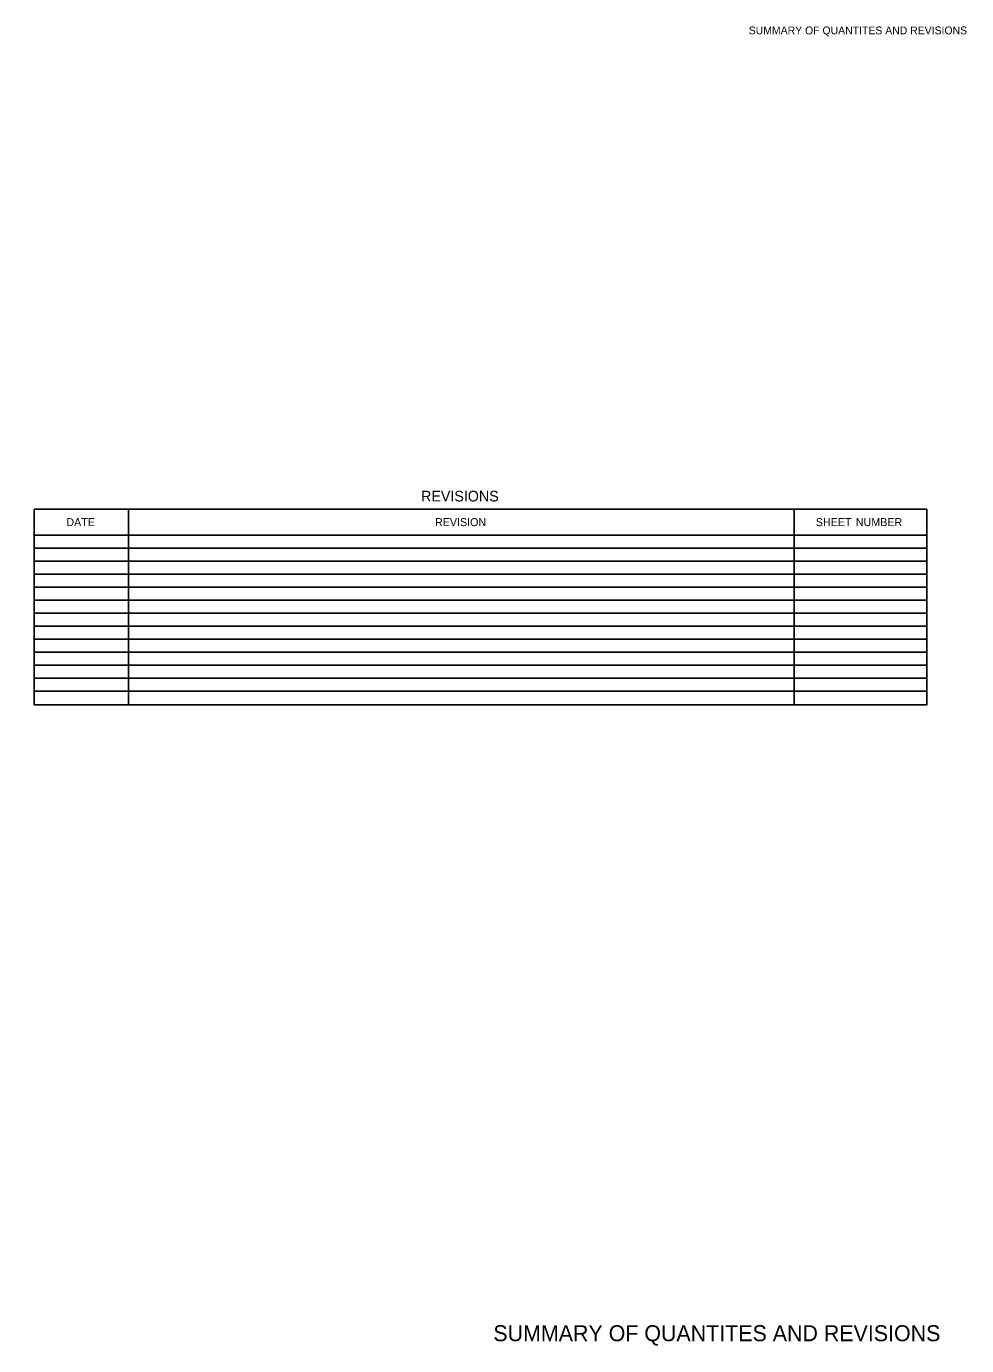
# Model space of a CAD drawing. Extents: x 977434 to 989596, y 1525697 to 1528336.
# Drawn here: x 988891 to 989596, y 1527332 to 1528321 of the extents above; entities that cross this region are included whole.
import ezdxf

# ---------------------------------------------------------------- set-up
doc = ezdxf.new("R2010")
doc.units = 0
for name, color, linetype in [('Default', 7, 'Continuous'), ('R_Border', 7, 'Continuous'), ('R_Border Prem', 7, 'Continuous')]:
    doc.layers.add(name, color=color, linetype=linetype)

msp = doc.modelspace()

# ---------------------------------------------------------------- linework, layer by layer
at = {"layer": 'Default'}
for p, q in [((988896.68, 1527958.98), (989566.02, 1527958.98)), ((988896.68, 1527958.98), (988967.37, 1527958.98)), ((988896.68, 1527812.24), (988896.68, 1527958.98)), ((988896.68, 1527812.24), (988896.68, 1527958.98)), ((988967.37, 1527812.24), (988967.37, 1527958.98)), ((989466.57, 1527958.98), (989566.02, 1527958.98)), ((989466.57, 1527939.48), (989466.57, 1527958.98)), ((989466.57, 1527812.24), (989466.57, 1527958.98)), ((989566.02, 1527812.24), (989566.02, 1527958.98)), ((989566.02, 1527812.24), (989566.02, 1527958.98)), ((988896.68, 1527939.48), (989566.02, 1527939.48)), ((988896.68, 1527929.73), (989566.02, 1527929.73)), ((988896.68, 1527919.98), (989566.02, 1527919.98)), ((988896.68, 1527910.23), (989566.02, 1527910.23)), ((988896.68, 1527900.48), (989566.02, 1527900.48)), ((988896.68, 1527890.73), (989566.02, 1527890.73)), ((988896.68, 1527880.98), (989566.02, 1527880.98)), ((988896.68, 1527871.23), (989566.02, 1527871.23)), ((988896.68, 1527861.48), (989566.02, 1527861.48)), ((988896.68, 1527851.73), (989566.02, 1527851.73)), ((988896.68, 1527841.98), (989566.02, 1527841.98)), ((988896.68, 1527832.23), (989566.02, 1527832.23)), ((988896.68, 1527822.48), (989566.02, 1527822.48)), ((988896.68, 1527812.24), (989566.02, 1527812.24))]:
    msp.add_line(p, q, dxfattribs=at)
at = {"layer": 'R_Border Prem'}
msp.add_line((988890.83, 1527978.48), (988890.83, 1527978.48), dxfattribs=at)

# ---------------------------------------------------------------- texts
at = {"layer": 'Default'}
for s, height, p in [('REVISIONS', 8, (989186.8, 1527964.73)), ('DATE', 6, (988920.82, 1527946.23)), ('REVISION', 6, (989197.27, 1527946.23)), ('SHEET', 6, (989482.86, 1527946.23)), (' NUMBER', 6, (989510.64, 1527946.23))]:
    msp.add_text(s, height=height, dxfattribs=at).set_placement(p)
at = {"layer": 'R_Border'}
msp.add_text('SUMMARY OF QUANTITES AND REVISIONS', height=12, rotation=360, dxfattribs=at).set_placement((989241.03, 1527335.24))
at = {"layer": 'R_Border Prem'}
msp.add_text('SUMMARY OF QUANTITES AND REVISIONS', height=5.862, rotation=360, dxfattribs=at).set_placement((989432.54, 1528314.92))

doc.saveas('drawing.dxf')
